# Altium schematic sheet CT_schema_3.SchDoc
size 314 x 312 mm
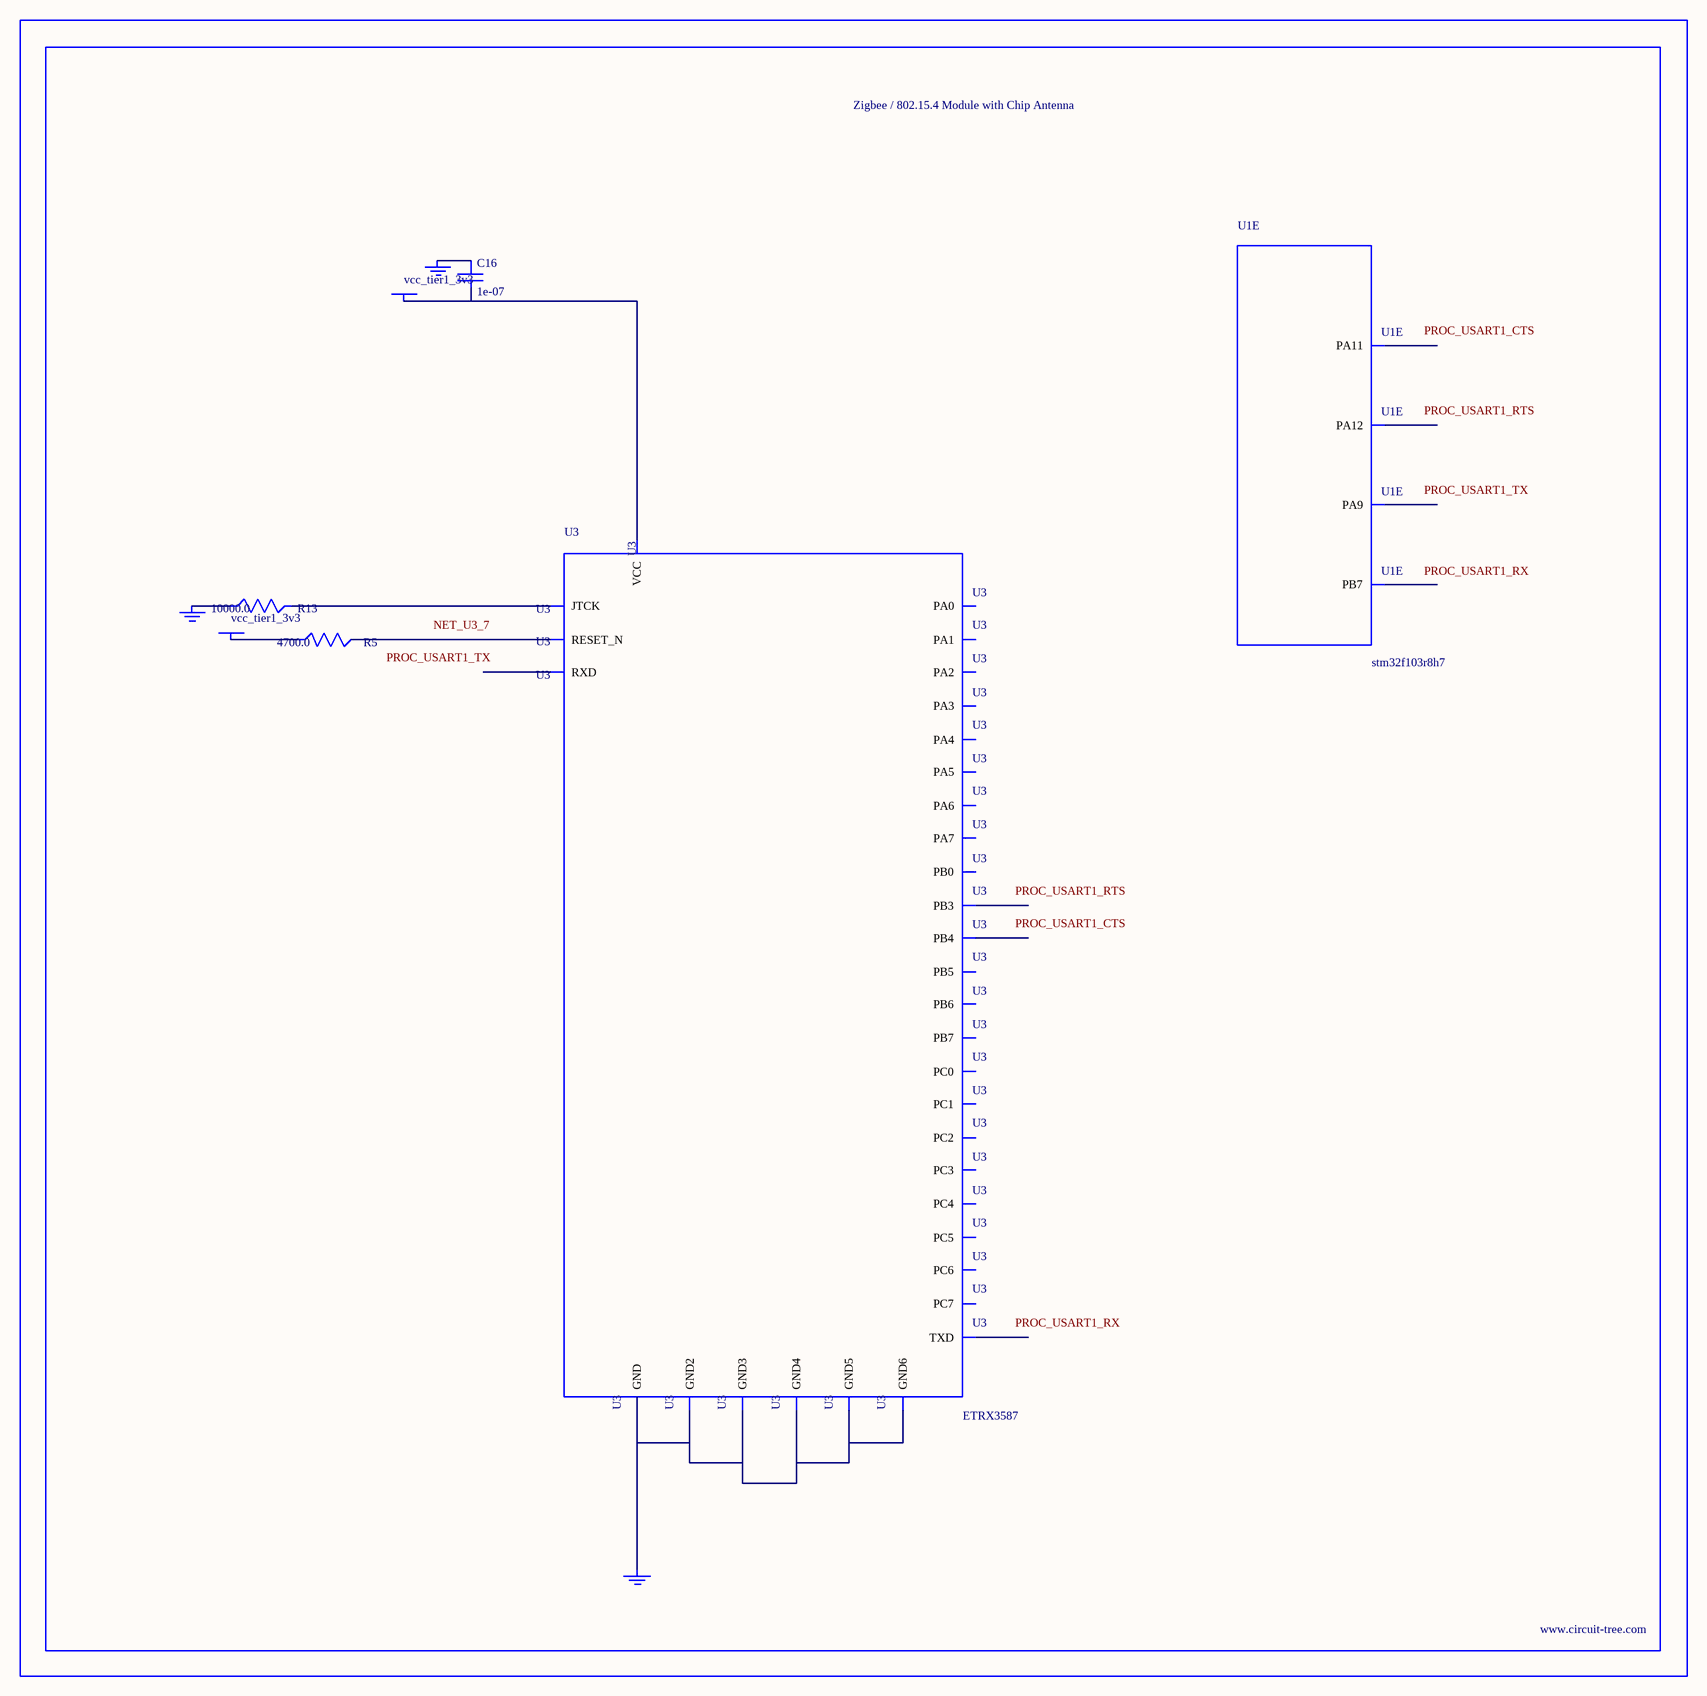
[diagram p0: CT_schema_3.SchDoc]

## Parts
BORDER2  (no value)
C16  1e-07  [C0402]
GND_INSTANCE_2_0  (no value)
GND_INSTANCE_2_1  (no value)
GND_INSTANCE_2_2  (no value)
POWER_INSTANCE_2_0  vcc_tier1_3v3
POWER_INSTANCE_2_1  vcc_tier1_3v3
R5  4700.0  [R0603]
R13  10000.0  [R0603]
U1  stm32f103r8h7  [TFBGA64]  (part E of 7)
U3  ETRX3587  [ETRX3587]

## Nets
NetC16_1: C16.1 GND_INSTANCE_2_1.0(GND)
NetC16_2: C16.2 POWER_INSTANCE_2_0.0(PWR) U3.32(VCC)
NetGND_INSTANCE_2_0_0: GND_INSTANCE_2_0.0(GND) R13.1
NetGND_INSTANCE_2_2_0: GND_INSTANCE_2_2.0(GND) U3.1(GND) U3.13(GND2) U3.19(GND3) U3.20(GND4) U3.31(GND5) U3.33(GND6)
NetPOWER_INSTANCE_2_1_0: POWER_INSTANCE_2_1.0(PWR) R5.1
NetR5_2: R5.2 U3.7(RESET_N)
NetR13_2: R13.2 U3.21(JTCK)

Not connected (* = marked no-connect by the designer): U1 B8(PA12) C3(PB7) C7(PA9) C8(PA11); U3 2(PC5) 3(PC6) 4(PC7) 5(PA7) 6(PB3) 8(PB4) 9(PA0) 10(PA1) 11(PA2) 12(PA3) 14(PA4) 15(PA5) 16(PA6) 17(TXD) 18(RXD) 22(PC2) 23(PC3) 24(PC4) 25(PB0) 26(PC1) 27(PC0) 28(PB7) 29(PB6) 30(PB5)

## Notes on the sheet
- Labels drawn without touching a wire or pin: NET_U3_7, PROC_USART1_CTS, PROC_USART1_RTS, PROC_USART1_RX, PROC_USART1_TX

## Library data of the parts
BORDER2 = BORDER_PAGE2
C16 = C0402C104K3RACTU
GND_INSTANCE_2_0-GND_INSTANCE_2_2 = GND
POWER_INSTANCE_2_0 POWER_INSTANCE_2_1 = PWR
R5 = RC0603JR-074K7L
R13 = RC0603JR-0710KL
